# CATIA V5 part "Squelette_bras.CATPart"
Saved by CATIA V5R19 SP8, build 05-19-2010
Part number: Squelette_bras
Bounding box of the stored display mesh (mm): x -200 to 200, y -600 to 70, z 1200 to 1365
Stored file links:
  G:\EU_thinkMotion\CFAO_2010\MMS_groupe2\MMS_groupe2\OK\nrosalie\nrosalie_cfao_support_d_arme_legere_final\Squelette_bras.CATPart
  G:\EU_thinkMotion\CFAO_2010\MMS_groupe2\MMS_groupe2\OK\nrosalie\nrosalie_cfao_support_d_arme_legere_final\Squelette_Systeme_de_visee.CATPart
  G:\EU_thinkMotion\CFAO_2010\MMS_groupe2\MMS_groupe2\OK\nrosalie\nrosalie_cfao_support_d_arme_legere_final\nrosalie_Support_d_arme_legere.CATProduct
  G:\EU_thinkMotion\CFAO_2010\MMS_groupe2\MMS_groupe2\OK\nrosalie\nrosalie_cfao_support_d_arme_legere_final\Squelette_piece_support.CATPart
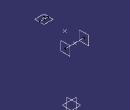
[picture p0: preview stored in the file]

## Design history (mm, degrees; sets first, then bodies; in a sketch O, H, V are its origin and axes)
External parameters (linked from other documents)
  `External.Position_en_-y_de_la_fixation_du_bras_du_canon_de_l'arme` = 600 mm
  `External.Hauteur_viseur_de_l'arme` = 1500 mm
  External.Hauteur_de_l_arme = 150 mm
  `External.Distance_selon_z_entre-centrage_arme_exterieur_axe_equilibrage_ext` = 50 mm
  External.Distance_minimale_selon_y_de_appui_inferieur_pres_de_la_colonne_de_l_arme = 150 mm
  External.Distance_minimale_selon_z_entre_dessous_arme_et_appui_inferieur_pres_de_la_colonne = 30 mm
  `External.Ecartement_des_poignés_selon_l_axe_x` = 70 mm
  `External.Distance_viseur_centre_poignés` = 300 mm
  `External.Ecartement_des_poignés_selon_l_axe_y` = 200 mm
  External.Largeur_de_l_arme = 100 mm
  External.Pourcentage_de_la_position_de_l_equilibrage_sur_la_piece_de_support_en_partant_axe_pivot_verticale = 10
Set1
  Point1: type OnPlane, Support yz-plane, H -600 {= -`External.Position_en_-y_de_la_fixation_du_bras_du_canon_de_l'arme`}, V 1365 {= `External.Hauteur_viseur_de_l'arme`-External.Hauteur_de_l_arme +15mm}, Direction (0, 1, 0)
  Line1: type Normal, RefPoint Point1, RefSkin Plane4, Start 50 {= `External.Distance_selon_z_entre-centrage_arme_exterieur_axe_equilibrage_ext`}, End 0
  Plane1: type Normal, Curve Line1, RefPoint vertex of Line1
  Line2: type Normal, RefPoint vertex of Line1, RefSkin yz-plane, Start -85 {= -External.Largeur_de_l_arme/2-35mm}, End 85 {= External.Largeur_de_l_arme /2+35mm}
  Point2: type OnPlane, Support yz-plane, H -150 {= -External.Distance_minimale_selon_y_de_appui_inferieur_pres_de_la_colonne_de_l_arme}, V 1320 {= `External.Hauteur_viseur_de_l'arme` -External.Hauteur_de_l_arme-External.Distance_minimale_selon_z_entre_dessous_arme_et_appui_inferieur_pres_de_la_colonne}, Direction (0, 1, 0)
  Point3: type OnPlane, Support yz-plane, H 70 {= `External.Ecartement_des_poignés_selon_l_axe_x`}, V 1200 {= `External.Hauteur_viseur_de_l'arme`-`External.Distance_viseur_centre_poignés`}, Direction (0, 1, 0)
  Line3: type Normal, RefPoint Point3, RefSkin yz-plane, Start 200 {= `External.Ecartement_des_poignés_selon_l_axe_y`}, End -200 {= -`External.Ecartement_des_poignés_selon_l_axe_y`}
  Plane2: type Normal, Curve Line3, RefPoint vertex of Line3
  Plane3: type Normal, Curve Line3, RefPoint vertex of Line3
Set2
  Plane4: linked copy from another document
  Line4: linked copy from another document
  Point4: linked copy from another document
Body1 (main body)
Relations
  Line2.Start = `Paramètres externes\Largeur_de_l_arme`+35MM (deactivated)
